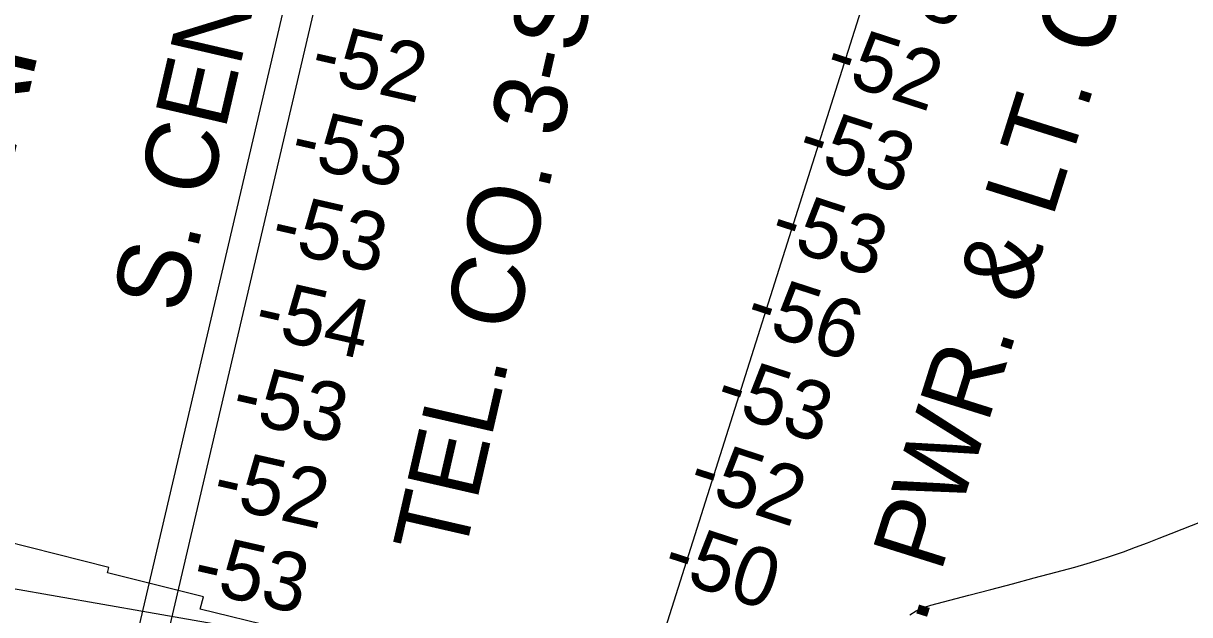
# Model space of a CAD drawing. Extents: x 3361039 to 3398939, y 576572 to 602007.
# Drawn here: x 3389365 to 3390699, y 585828 to 586504 of the extents above; entities that cross this region are included whole.
import ezdxf

# ---------------------------------------------------------------- set-up
doc = ezdxf.new("R2010")
doc.units = 0
for name, color, linetype in [('V-CHAN-NAID', 7, 'Continuous'), ('V-RIVR-RANG', 7, 'Continuous'), ('V-RRAP-RVMT', 7, 'Continuous'), ('V-TOPO-MAJR', 7, 'Continuous'), ('V-UTIL-IDEN', 7, 'Continuous'), ('V-UTIL-LINE', 7, 'Continuous')]:
    doc.layers.add(name, color=color, linetype=linetype)

msp = doc.modelspace()

# ---------------------------------------------------------------- linework, layer by layer
at = {"layer": 'V-RRAP-RVMT'}
msp.add_lwpolyline([(3389654.5, 585812.6), (3389567.1, 585833.8), (3389570.7, 585848.1), (3389461.1, 585875.4), (3389462.6, 585881.3), (3389311.7, 585919.5), (3389309, 585908.9), (3389166.8, 585945.5), (3389165.3, 585939.7), (3389027.2, 585965.9), (3389026.6, 585962.6), (3388892.8, 585984), (3388894.4, 585993.6), (3388754.7, 586017.8), (3388756.3, 586028.6), (3388610.6, 586048.8), (3388611.3, 586055.9), (3388473.2, 586069.2)], dxfattribs=at)
at = {"layer": 'V-TOPO-MAJR'}
for points in [[(3390378.5, 585827.2), (3390385.9, 585831.9), (3390394, 585835.6), (3390402.5, 585838.4), (3390446.1, 585849.8), (3390471, 585856.3), (3390495.9, 585862.9), (3390520.8, 585869.5), (3390545.6, 585876.1), (3390567.1, 585881.9), (3390581.2, 585885.9), (3390595.2, 585890.1), (3390609, 585894.7), (3390622.8, 585899.5), (3390636.5, 585904.6), (3390650.2, 585909.7), (3390663.8, 585915), (3390677.5, 585920.3), (3390749, 585948.5)], [(3389141.9, 585894.3), (3389612.3, 585812.1)]]:
    msp.add_lwpolyline(points, dxfattribs=at)
at = {"layer": 'V-UTIL-LINE'}
for p, q in [((3390065.6, 588240.1), (3389380, 585315.4)), ((3390100.6, 588240.1), (3389414.9, 585315.4)), ((3389912.9, 585222.9), (3390850.7, 588188))]:
    msp.add_line(p, q, dxfattribs=at)

# ---------------------------------------------------------------- texts
at = {"layer": 'V-CHAN-NAID'}
msp.add_text('BAYOU LAFOURCHE INTAKE (175.4) (2)', height=100, rotation=76.7837, dxfattribs=at).set_placement((3389221.8, 585787.2))
at = {"layer": 'V-RIVR-RANG'}
for s, rotation, p in [('-53', 341.9484, (3390309.1, 586538)), ('-52', 347.1806, (3389690.8, 586441.2)), ('-52', 341.9484, (3390278.4, 586442.8)), ('-53', 347.1806, (3389667.8, 586343.9)), ('-53', 341.9484, (3390246.7, 586348)), ('-53', 347.1806, (3389645.4, 586246.4)), ('-53', 341.9484, (3390215.5, 586253)), ('-54', 347.1806, (3389626.3, 586148.2)), ('-56', 341.9484, (3390187.3, 586157)), ('-53', 347.1806, (3389600.6, 586051.5)), ('-53', 341.9484, (3390153, 586063)), ('-52', 341.9484, (3390122.3, 585967.8)), ('-52', 347.1806, (3389578.6, 585954)), ('-50', 341.9484, (3390092.8, 585872.2)), ('-53', 347.1806, (3389555.7, 585856.6))]:
    msp.add_text(s, height=67, rotation=rotation, dxfattribs=at).set_placement(p)
at = {"layer": 'V-UTIL-IDEN'}
for s, rotation, p in [('S. CENTRAL BELL', 76.9135, (3389546.6, 586170)), ('TEL. CO. 3-SUB CABLE', 77.076, (3389868.1, 585889.9)), ('LA. PWR. & LT. CO.', 72.5093, (3390354.4, 585686))]:
    msp.add_text(s, height=83, rotation=rotation, dxfattribs=at).set_placement(p)

doc.saveas('drawing.dxf')
